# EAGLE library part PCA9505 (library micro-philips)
40-bit I2C-bus I/O port with /RESET, /OE and /INT The 9505 has 100k ohm pull-ups on IO pins. Source: http://www.nxp.com/acrobat_download/datasheets/PCA9505_9506_3.pdf
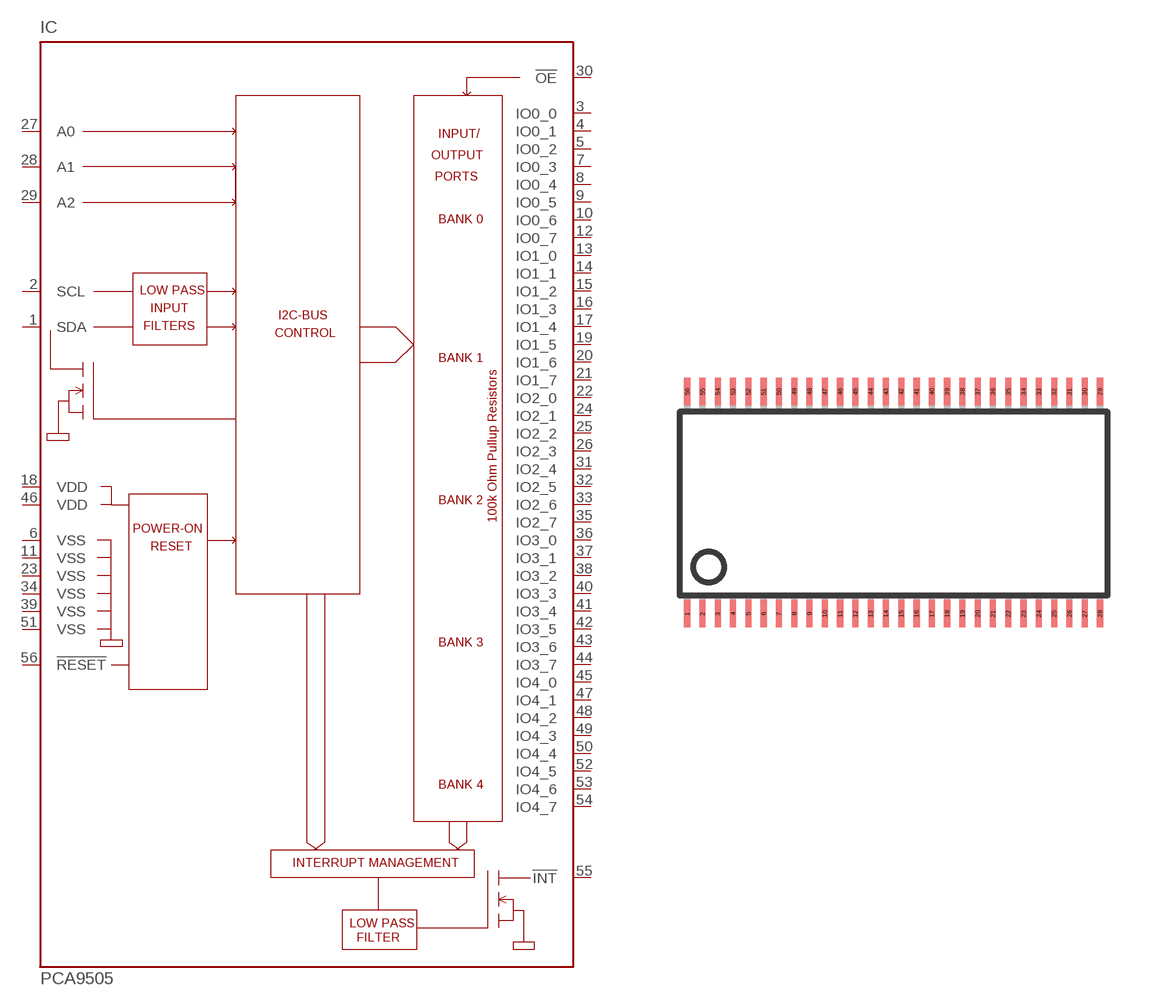
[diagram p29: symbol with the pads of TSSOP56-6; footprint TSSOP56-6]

Designator prefix IC

## PCA9505 (MPN: PCA9505DGG,118; OC_FARNELL: unknown; OC_NEWARK: 70R6450)  [TSSOP56-6]
1  SDA
2  SCL  in
3  IO0_0
4  IO0_1
5  IO0_2
6  VSS  pwr
7  IO0_3
8  IO0_4
9  IO0_5
10  IO0_6
11  VSS  pwr
12  IO0_7
13  IO1_0
14  IO1_1
15  IO1_2
16  IO1_3
17  IO1_4
18  VDD  pwr
19  IO1_5
20  IO1_6
21  IO1_7
22  IO2_0
23  VSS  pwr
24  IO2_1
25  IO2_2
26  IO2_3
27  A0  in
28  A1  in
29  A2  in
30  !OE  in
31  IO2_4
32  IO2_5
33  IO2_6
34  VSS  pwr
35  IO2_7
36  IO3_0
37  IO3_1
38  IO3_2
39  VSS  pwr
40  IO3_3
41  IO3_4
42  IO3_5
43  IO3_6
44  IO3_7
45  IO4_0
46  VDD  pwr
47  IO4_1
48  IO4_2
49  IO4_3
50  IO4_4
51  VSS  pwr
52  IO4_5
53  IO4_6
54  IO4_7
55  !INT  in
56  !RESET  in

## Footprint TSSOP56-6 (pad centres in mm)
TSSOP56 Plastic thin shrink small outline package; 56 leads; body width 6.1mm AKA SOT364-1 Source: http://www.nxp.com/acrobat_download/datasheets/PCA9505_9506_3.pdf
smd 0.2 x 0.9: 1 -6.75,-3.6; 2 -6.25,-3.6; 3 -5.75,-3.6; 4 -5.25,-3.6; 5 -4.75,-3.6; 6 -4.25,-3.6; 7 -3.75,-3.6; 8 -3.25,-3.6; 9 -2.75,-3.6; 10 -2.25,-3.6; 11 -1.75,-3.6; 12 -1.25,-3.6; 13 -0.75,-3.6; 14 -0.25,-3.6; 15 0.25,-3.6; 16 0.75,-3.6; 17 1.25,-3.6; 18 1.75,-3.6; 19 2.25,-3.6; 20 2.75,-3.6; 21 3.25,-3.6; 22 3.75,-3.6; 23 4.25,-3.6; 24 4.75,-3.6; 25 5.25,-3.6; 26 5.75,-3.6; 27 6.25,-3.6; 28 6.75,-3.6; 29 6.75,3.66; 30 6.25,3.66; 31 5.75,3.66; 32 5.25,3.66; 33 4.75,3.66; 34 4.25,3.66; 35 3.75,3.66; 36 3.25,3.66; 37 2.75,3.66; 38 2.25,3.66; 39 1.75,3.66; 40 1.25,3.66; 41 0.75,3.66; 42 0.25,3.66; 43 -0.25,3.66; 44 -0.75,3.66; 45 -1.25,3.66; 46 -1.75,3.66; 47 -2.25,3.66; 48 -2.75,3.66; 49 -3.25,3.66; 50 -3.75,3.66; 51 -4.25,3.66; 52 -4.75,3.66; 53 -5.25,3.66; 54 -5.75,3.66; 55 -6.25,3.66; 56 -6.75,3.66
